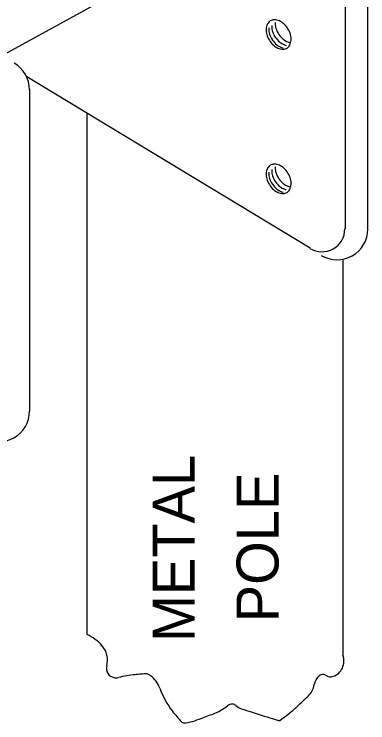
# Model space of a CAD drawing. Extents: x -1551.93 to -1544.71, y 2060.77 to 2070.61.
# Drawn here: x -1548.545 to -1548.04, y 2068.707 to 2069.721 of the extents above; entities that cross this region are included whole.
import ezdxf

# ---------------------------------------------------------------- set-up
doc = ezdxf.new("R2010")
doc.units = 0
for name, color, linetype in [('DETL-DIMS', 7, 'Continuous'), ('DETL-LINE', 7, 'Continuous'), ('DETL-NOTE', 7, 'Continuous')]:
    doc.layers.add(name, color=color, linetype=linetype)

msp = doc.modelspace()

# ---------------------------------------------------------------- linework, layer by layer
at = {"layer": 'DETL-DIMS'}
msp.add_line((-1548.5636, 2069.661), (-1548.1536, 2069.887), dxfattribs=at)
at = {"layer": 'DETL-LINE'}
for p, q in [((-1548.0726, 2069.874), (-1548.0726, 2069.414)), ((-1548.0406, 2069.874), (-1548.0406, 2069.413)), ((-1548.1226, 2069.386), (-1548.5276, 2069.631)), ((-1548.5236, 2069.613), (-1548.5236, 2069.153)), ((-1548.4416, 2069.579), (-1548.4416, 2068.834)), ((-1548.0756, 2069.37), (-1548.0756, 2068.804))]:
    msp.add_line(p, q, dxfattribs=at)
for points in [[(-1548.3556, 2068.777), (-1548.3556, 2068.777)], [(-1548.3966, 2068.772), (-1548.3966, 2068.772)]]:
    msp.add_lwpolyline(points, dxfattribs=at)
for centre, radius, start, end in [((-1548.1737, 2069.7018), 0.0109, 121.5859, 152.7723), ((-1548.1737, 2069.7018), 0.0109, 90.3995, 121.5859), ((-1548.1736, 2069.6951), 0.0175, 65.9703, 90.3995), ((-1548.1549, 2069.7077), 0.0175, 175.5761, 179.972), ((-1548.1763, 2069.6891), 0.0242, 47.4114, 65.9703), ((-1548.1678, 2069.6988), 0.0175, 152.7723, 177.2015), ((-1548.1611, 2069.6984), 0.0242, 177.2015, 195.7604), ((-1548.1641, 2069.6998), 0.0175, 175.5761, 179.972), ((-1548.1575, 2069.6998), 0.0242, 179.972, 198.5308), ((-1548.1599, 2069.7035), 0.0175, 175.5761, 179.972), ((-1548.1532, 2069.7035), 0.0242, 179.972, 198.5308), ((-1548.1483, 2069.7077), 0.0242, 179.972, 198.5308), ((-1548.1397, 2069.7106), 0.0332, 198.5308, 214.3563), ((-1548.1824, 2069.6825), 0.0332, 31.5859, 47.4114), ((-1548.1824, 2069.6825), 0.0332, 15.7604, 31.5859), ((-1548.1525, 2069.7009), 0.0332, 195.7604, 211.5859), ((-1548.1489, 2069.7026), 0.0332, 198.5308, 214.3563), ((-1548.1447, 2069.7064), 0.0332, 198.5308, 214.3563), ((-1548.1397, 2069.7106), 0.0332, 214.3563, 230.1818), ((-1548.1738, 2069.6849), 0.0242, 357.2015, 15.7604), ((-1548.1525, 2069.7009), 0.0332, 211.5859, 227.4114), ((-1548.1489, 2069.7026), 0.0332, 214.3563, 230.1818), ((-1548.1447, 2069.7064), 0.0332, 214.3563, 230.1818), ((-1548.1505, 2069.6995), 0.0242, 230.1818, 248.7407), ((-1548.1455, 2069.7037), 0.0242, 230.1818, 248.7407), ((-1548.1479, 2069.6975), 0.0175, 248.7407, 257.6351), ((-1548.1672, 2069.6846), 0.0175, 332.7723, 357.2015), ((-1548.1586, 2069.6943), 0.0242, 227.4114, 245.9703), ((-1548.1547, 2069.6957), 0.0242, 230.1818, 248.7407), ((-1548.1613, 2069.6882), 0.0175, 245.9703, 270.3995), ((-1548.1571, 2069.6896), 0.0175, 248.7407, 257.6351), ((-1548.1612, 2069.6815), 0.0109, 270.3995, 301.5859), ((-1548.1529, 2069.6933), 0.0175, 248.7407, 257.6351), ((-1548.1612, 2069.6815), 0.0109, 301.5859, 332.7723), ((-1548.5673, 2069.6127), 0.0438, 0, 59.8138), ((-1548.1737, 2069.4954), 0.0109, 90.3995, 121.5859), ((-1548.1736, 2069.4887), 0.0175, 65.9703, 90.3995), ((-1548.1678, 2069.4923), 0.0175, 152.7723, 177.2015), ((-1548.1737, 2069.4954), 0.0109, 121.5859, 152.7723), ((-1548.1599, 2069.4971), 0.0175, 175.5761, 179.972), ((-1548.1532, 2069.4971), 0.0242, 179.972, 198.5308), ((-1548.1549, 2069.5013), 0.0175, 175.5761, 179.972), ((-1548.1483, 2069.5013), 0.0242, 179.972, 198.5308), ((-1548.1763, 2069.4827), 0.0242, 47.4114, 65.9703), ((-1548.1824, 2069.476), 0.0332, 31.5859, 47.4114), ((-1548.1611, 2069.492), 0.0242, 177.2015, 195.7604), ((-1548.1641, 2069.4934), 0.0175, 175.5761, 179.972), ((-1548.1575, 2069.4934), 0.0242, 179.972, 198.5308), ((-1548.1489, 2069.4962), 0.0332, 198.5308, 214.3563), ((-1548.1447, 2069.4999), 0.0332, 198.5308, 214.3563), ((-1548.1397, 2069.5042), 0.0332, 198.5308, 214.3563), ((-1548.1824, 2069.476), 0.0332, 15.7604, 31.5859), ((-1548.1525, 2069.4945), 0.0332, 195.7604, 211.5859), ((-1548.1525, 2069.4945), 0.0332, 211.5859, 227.4114), ((-1548.1489, 2069.4962), 0.0332, 214.3563, 230.1818), ((-1548.1447, 2069.4999), 0.0332, 214.3563, 230.1818), ((-1548.1397, 2069.5042), 0.0332, 214.3563, 230.1818), ((-1548.1455, 2069.4973), 0.0242, 230.1818, 248.7407), ((-1548.1672, 2069.4782), 0.0175, 332.7723, 357.2015), ((-1548.1738, 2069.4785), 0.0242, 357.2015, 15.7604), ((-1548.1586, 2069.4878), 0.0242, 227.4114, 245.9703), ((-1548.1547, 2069.4893), 0.0242, 230.1818, 248.7407), ((-1548.1613, 2069.4818), 0.0175, 245.9703, 270.3995), ((-1548.1505, 2069.493), 0.0242, 230.1818, 248.7407), ((-1548.1571, 2069.4831), 0.0175, 248.7407, 257.6351), ((-1548.1612, 2069.4751), 0.0109, 270.3995, 301.5859), ((-1548.1529, 2069.4869), 0.0175, 248.7407, 257.6351), ((-1548.1612, 2069.4751), 0.0109, 301.5859, 332.7723), ((-1548.1479, 2069.4911), 0.0175, 248.7407, 257.6351), ((-1548.1057, 2069.4138), 0.0328, 238.7649, 0), ((-1548.0838, 2069.4133), 0.0438, 238.7649, 0), ((-1548.5673, 2069.153), 0.0438, 238.7649, 0), ((-1548.4706, 2068.7717), 0.0685, 53.2214, 64.6379), ((-1548.4673, 2068.7762), 0.0629, 41.3078, 53.2214), ((-1548.444, 2068.7967), 0.0319, 345.1585, 41.3078), ((-1548.0985, 2068.7957), 0.0243, 335.2783, 19.3236), ((-1548.4001, 2068.7851), 0.0135, 165.1585, 257.8422), ((-1548.3512, 2068.5817), 0.1955, 96.2943, 99.8161), ((-1548.3512, 2068.5817), 0.1955, 93.7951, 96.2943), ((-1548.3512, 2068.5817), 0.1955, 91.2959, 93.7951), ((-1548.3955, 2068.6868), 0.0988, 63.4986, 66.1916), ((-1548.1045, 2068.7692), 0.0072, 55.9985, 128.4522), ((-1548.0968, 2068.7949), 0.0225, 289.4361, 335.2783), ((-1548.4006, 2068.783), 0.0114, 257.8422, 270.0637), ((-1548.4006, 2068.8067), 0.0351, 270.0637, 277.01), ((-1548.3512, 2068.5817), 0.1955, 99.8161, 103.3379), ((-1548.3542, 2068.7697), 0.0061, 52.6516, 63.4986), ((-1548.3739, 2068.7438), 0.0387, 19.7644, 52.6516), ((-1548.0958, 2068.7582), 0.0211, 128.4522, 170.3361), ((-1548.0935, 2068.7854), 0.0124, 235.9985, 289.4361), ((-1548.2269, 2068.7966), 0.1175, 199.7644, 218.4505), ((-1548.1457, 2068.7667), 0.0295, 315.1086, 350.3361), ((-1548.4597, 2069.0795), 0.4726, 312.3739, 315.1086), ((-1548.2777, 2068.7745), 0.0567, 292.4591, 310.7942), ((-1548.2342, 2068.724), 0.00995, 86.0999, 130.7942), ((-1548.2341, 2068.7253), 0.00868, 48.4919, 86.0999), ((-1548.2136, 2068.7486), 0.0224, 228.4919, 251.6634), ((-1547.675, 2070.3735), 1.7343, 251.6634, 252.1512), ((-1548.3109, 2068.9164), 0.2519, 308.628, 312.3739), ((-1548.0948, 2068.9015), 0.2863, 218.4505, 222.271), ((-1548.5067, 2069.3283), 0.6559, 290.6936, 292.4591), ((-1546.8351, 2072.9817), 4.4743, 252.1512, 252.4549), ((-1547.7797, 2069.9943), 1.3412, 252.4549, 253.1362), ((-1548.2958, 2068.8975), 0.2276, 304.8415, 308.628), ((-1548.303, 2068.7122), 0.00483, 222.271, 252.0063), ((-1548.3015, 2068.7169), 0.00978, 252.0063, 278.7162), ((-1548.312, 2068.7855), 0.0792, 278.7162, 288.0272), ((-1548.3765, 2068.9837), 0.2876, 288.0272, 290.6936), ((-1548.1636, 2068.7278), 0.0178, 253.1362, 259.0548), ((-1548.1666, 2068.712), 0.00164, 259.0548, 304.8415)]:
    msp.add_arc(centre, radius, start, end, dxfattribs=at)

# ---------------------------------------------------------------- texts
at = {"layer": 'DETL-NOTE'}
for s, p in [('METAL', (-1548.2876, 2068.823)), ('POLE', (-1548.1676, 2068.851))]:
    msp.add_text(s, height=0.06, rotation=90, dxfattribs=at).set_placement(p)

doc.saveas('drawing.dxf')
